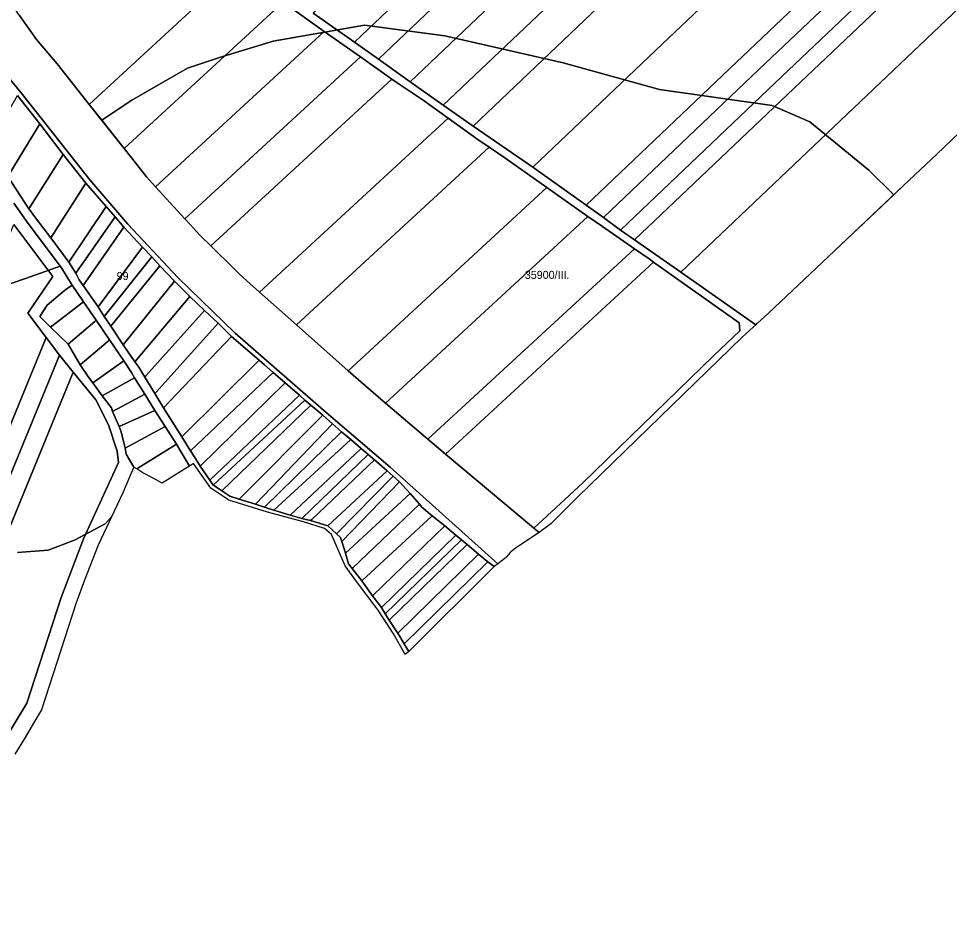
# Model space of a CAD drawing. Extents: x -545779 to -541342, y -1153413 to -1149956.
# Drawn here: x -543424 to -542843, y -1152006 to -1151443 of the extents above; entities that cross this region are included whole.
import ezdxf

# ---------------------------------------------------------------- set-up
doc = ezdxf.new("R2010")
doc.units = 0
for name, color, linetype in [('95560013', 7, 'Continuous'), ('95610013', 7, 'Continuous'), ('95620013', 7, 'Continuous'), ('95640013', 7, 'Continuous'), ('95660013', 7, 'Continuous')]:
    doc.layers.add(name, color=color, linetype=linetype)

msp = doc.modelspace()

# ---------------------------------------------------------------- linework, layer by layer
at = {"layer": '95560013'}
for points in [[(-543240.37, -1151439.86), (-543122.07, -1151327.37), (-543086.44, -1151336.23), (-543214.46, -1151457.97)], [(-543214.46, -1151457.97), (-543086.44, -1151336.23), (-543065.8, -1151341.37), (-543199.56, -1151468.55)], [(-543179.72, -1151482.68), (-543199.56, -1151468.55), (-543065.8, -1151341.37), (-543038.3, -1151348.21)], [(-543009.67, -1151355.33), (-543084.36, -1151426.35), (-543159.05, -1151497.37), (-543179.72, -1151482.68), (-543038.3, -1151348.21)], [(-543062.24, -1151436.05), (-543140.42, -1151510.39), (-543159.05, -1151497.37), (-543084.36, -1151426.35), (-543009.67, -1151355.33), (-542984.05, -1151361.71)], [(-543140.42, -1151510.39), (-543062.24, -1151436.05), (-542984.05, -1151361.71), (-542933.06, -1151374.39), (-543018.07, -1151455.22), (-543103.08, -1151536.05)], [(-543423.58, -1151441.25), (-543430.04, -1151432.08), (-543356.46, -1151364.23), (-543288.42, -1151412.25), (-543380.16, -1151496.84), (-543386.97, -1151488.23), (-543400.2, -1151471.61), (-543412.96, -1151456.3)], [(-543103.08, -1151536.05), (-543018.07, -1151455.22), (-542933.06, -1151374.39), (-542927.73, -1151375.72), (-542900.97, -1151380.24), (-542882.37, -1151381.53), (-542976.06, -1151470.62), (-543069.78, -1151559.73)], [(-542882.37, -1151381.53), (-542864.78, -1151382.75), (-542961.9, -1151475.1), (-543059.01, -1151567.44), (-543069.78, -1151559.73), (-542976.06, -1151470.62)], [(-542846.78, -1151383.71), (-542947.57, -1151479.54), (-543048.35, -1151575.37), (-543059.01, -1151567.44), (-542961.9, -1151475.1), (-542864.78, -1151382.75)], [(-542790.26, -1151387.63), (-542786.61, -1151388.71), (-542898.64, -1151495.22), (-543010.58, -1151601.66), (-543039.61, -1151581.56), (-542935.84, -1151482.89), (-542832.06, -1151384.22), (-542810.18, -1151384.97), (-542802.82, -1151385.95)], [(-542871.69, -1151547.61), (-542922.37, -1151595.59), (-542955.86, -1151627.29), (-542962.76, -1151633.49), (-542963.34, -1151634.01), (-542963.9, -1151634.52), (-543010.58, -1151601.66), (-542898.64, -1151495.22), (-542786.61, -1151388.71), (-542775.01, -1151392.15), (-542752.94, -1151403.28), (-542735.72, -1151413.15), (-542737.87, -1151417.23), (-542736.37, -1151418.2), (-542850.69, -1151527.98)], [(-543259.04, -1151432.91), (-543358.33, -1151524.47), (-543380.16, -1151496.84), (-543288.42, -1151412.25)], [(-543344.41, -1151542.05), (-543350.42, -1151534.47), (-543358.33, -1151524.47), (-543259.04, -1151432.91), (-543233.34, -1151451.27), (-543338.64, -1151548.36)], [(-543320.46, -1151568.25), (-543338.64, -1151548.36), (-543233.34, -1151451.27), (-543210.79, -1151467.12)], [(-543311.26, -1151578.3), (-543316.87, -1151572.17), (-543320.46, -1151568.25), (-543210.79, -1151467.12), (-543191.19, -1151481.04), (-543304.19, -1151585.24)], [(-543289.4, -1151599.75), (-543304.19, -1151585.24), (-543191.19, -1151481.04), (-543187.9, -1151483.38), (-543171.65, -1151494.16), (-543155.98, -1151505.49), (-543273.77, -1151614.1), (-543279.62, -1151608.92), (-543286.22, -1151602.87)], [(-543155.98, -1151505.49), (-543138.08, -1151518.43), (-543130.45, -1151523.63), (-543250.73, -1151634.54), (-543273.77, -1151614.1)], [(-543218.4, -1151663.21), (-543250.73, -1151634.54), (-543130.45, -1151523.63), (-543120.6, -1151530.35), (-543094.32, -1151548.8)], [(-543195.12, -1151683.41), (-543207.39, -1151672.98), (-543218.4, -1151663.21), (-543094.32, -1151548.8), (-543068.68, -1151566.81)], [(-543418.53, -1151627.26), (-543406.97, -1151642.49), (-543468.49, -1151792.18), (-543530.01, -1151941.87), (-543533.97, -1151930.97), (-543541.88, -1151911.96), (-543552.58, -1151876.88), (-543489.89, -1151724.34), (-543427.2, -1151571.8), (-543402.91, -1151604.4)], [(-543168.57, -1151706), (-543039.57, -1151587.04), (-543030.45, -1151593.35), (-543027.64, -1151595.49), (-543157.6, -1151715.34), (-543157.86, -1151715.12)], [(-542990.29, -1151653.95), (-543071.95, -1151733.2), (-543102.39, -1151761.68), (-543102.65, -1151761.47), (-543157.6, -1151715.34), (-543027.64, -1151595.49), (-543013.28, -1151605.56), (-542974.24, -1151633.22), (-542973.87, -1151638.29)], [(-543398.65, -1151653.46), (-543461.32, -1151805.95), (-543523.99, -1151958.44), (-543530.01, -1151941.87), (-543468.49, -1151792.18), (-543406.97, -1151642.49)], [(-543521.45, -1151965.43), (-543523.99, -1151958.44), (-543461.32, -1151805.95), (-543398.65, -1151653.46), (-543390.07, -1151664.07), (-543453.49, -1151818.38), (-543516.9, -1151972.68)], [(-543479.1, -1152005.99), (-543483.3, -1152003.71), (-543498.41, -1151992.69), (-543511.62, -1151981.09), (-543516.9, -1151972.68), (-543453.49, -1151818.38), (-543390.07, -1151664.07), (-543376.03, -1151681.34), (-543368.01, -1151696.98), (-543362.61, -1151713.54), (-543361.78, -1151720.51), (-543383.75, -1151768.25), (-543397.66, -1151804.81), (-543419.12, -1151870.85), (-543435.52, -1151898.22), (-543452.76, -1151939.02), (-543469.17, -1151983.54)]]:
    msp.add_lwpolyline(points, close=True, dxfattribs=at)
at = {"layer": '95610013'}
for points in [[(-542947.57, -1151479.54), (-542846.78, -1151383.71), (-542832.06, -1151384.22), (-542935.84, -1151482.89), (-543039.61, -1151581.56), (-543048.35, -1151575.37)], [(-543168.57, -1151706), (-543195.12, -1151683.41), (-543068.68, -1151566.81), (-543059.58, -1151573.2), (-543039.57, -1151587.04)]]:
    msp.add_lwpolyline(points, close=True, dxfattribs=at)
at = {"layer": '95620013'}
for points in [[(-543431.06, -1151541.91), (-543443.74, -1151523.48), (-543424.88, -1151491.22), (-543411.05, -1151509.1)], [(-543396.33, -1151528.09), (-543417.85, -1151562.13), (-543431.06, -1151541.91), (-543411.05, -1151509.1)], [(-543417.85, -1151562.13), (-543396.33, -1151528.09), (-543382.25, -1151546.08), (-543404.04, -1151580.22), (-543413.66, -1151567.75), (-543417.06, -1151563.2)], [(-543392.91, -1151595.33), (-543404.04, -1151580.22), (-543382.25, -1151546.08), (-543369.53, -1151560.74)], [(-543388.58, -1151602.2), (-543392.91, -1151595.33), (-543369.53, -1151560.74), (-543363.99, -1151567.2)], [(-543363.99, -1151567.2), (-543358.52, -1151573.53), (-543383.9, -1151609.97), (-543386.4, -1151606.53), (-543388.58, -1151602.2)], [(-543374.64, -1151623.4), (-543383.9, -1151609.97), (-543358.52, -1151573.53), (-543346.88, -1151586.09)], [(-543370.78, -1151629.43), (-543374.64, -1151623.4), (-543346.88, -1151586.09), (-543341.09, -1151592.14)], [(-543336, -1151597.73), (-543366.59, -1151635.38), (-543370.78, -1151629.43), (-543341.09, -1151592.14)], [(-543336, -1151597.73), (-543326.96, -1151607.22), (-543358.99, -1151647.05), (-543366.59, -1151635.38)], [(-543383.68, -1151620.16), (-543404.26, -1151636.1), (-543410.94, -1151629.34), (-543406.39, -1151622.22), (-543395.57, -1151613.08), (-543390.73, -1151609.82)], [(-543326.96, -1151607.22), (-543317.23, -1151616.88), (-543351.67, -1151657.74), (-543358.99, -1151647.05)], [(-543351.67, -1151657.74), (-543317.23, -1151616.88), (-543308.05, -1151625.71), (-543344.71, -1151666.45), (-543345.38, -1151667.2), (-543349.1, -1151661.08)], [(-543393.26, -1151646.72), (-543404.26, -1151636.1), (-543383.68, -1151620.16), (-543375.77, -1151631.75), (-543376.67, -1151632.52)], [(-543338.41, -1151676.71), (-543339.11, -1151677.5), (-543345.38, -1151667.2), (-543344.71, -1151666.45), (-543308.05, -1151625.71), (-543299.7, -1151633.54)], [(-543375.77, -1151631.75), (-543367.41, -1151644), (-543368.27, -1151644.72), (-543385.79, -1151659.49), (-543393.26, -1151646.72), (-543376.67, -1151632.52)], [(-543339.11, -1151677.5), (-543338.41, -1151676.71), (-543299.7, -1151633.54), (-543291.25, -1151641.87), (-543333.74, -1151686.33)], [(-543367.41, -1151644), (-543358.52, -1151657.03), (-543377.93, -1151670.81), (-543380.54, -1151667.3), (-543385.79, -1151659.49), (-543368.27, -1151644.72)], [(-543273.98, -1151656.74), (-543322.26, -1151704.61), (-543333.74, -1151686.33), (-543291.25, -1151641.87)], [(-543351.88, -1151667.61), (-543372.12, -1151679.02), (-543377.93, -1151670.81), (-543358.52, -1151657.03), (-543353.82, -1151664.27)], [(-543322.26, -1151704.61), (-543273.98, -1151656.74), (-543270.64, -1151659.61), (-543265.26, -1151664.33), (-543316.8, -1151713.2)], [(-543257.86, -1151670.85), (-543310.9, -1151722.83), (-543312.74, -1151719.8), (-543316.8, -1151713.2), (-543265.26, -1151664.33)], [(-543365.53, -1151688.62), (-543366.14, -1151686.46), (-543372.12, -1151679.02), (-543351.88, -1151667.61), (-543345.5, -1151677.89)], [(-543248.85, -1151678.58), (-543304.87, -1151731.69), (-543310.9, -1151722.83), (-543257.86, -1151670.85)], [(-543365.53, -1151688.62), (-543345.5, -1151677.89), (-543339.14, -1151688.04), (-543361.47, -1151698.1)], [(-543304.87, -1151731.69), (-543248.85, -1151678.58), (-543245.42, -1151681.55), (-543302.64, -1151734.66)], [(-543302.64, -1151734.66), (-543245.42, -1151681.55), (-543241.77, -1151684.73), (-543297.28, -1151738.29), (-543301.9, -1151735.16)], [(-543332.76, -1151698.02), (-543357.78, -1151711.52), (-543360.15, -1151701.38), (-543361.47, -1151698.1), (-543339.14, -1151688.04)], [(-543286.4, -1151743.51), (-543292.3, -1151741.64), (-543297.28, -1151738.29), (-543241.77, -1151684.73), (-543234.33, -1151691.06)], [(-543234.33, -1151691.06), (-543228.27, -1151696.33), (-543276.32, -1151746.7), (-543286.4, -1151743.51)], [(-543349.79, -1151724.17), (-543350.45, -1151724.58), (-543352.26, -1151723.45), (-543357.05, -1151715.3), (-543357.78, -1151711.52), (-543332.76, -1151698.02), (-543325.58, -1151709.18)], [(-543228.27, -1151696.33), (-543222.62, -1151701.37), (-543270.61, -1151748.52), (-543276.32, -1151746.7)], [(-543222.62, -1151701.37), (-543216.77, -1151706.3), (-543264.78, -1151750.28), (-543268.23, -1151749.27), (-543270.61, -1151748.52)], [(-543346.65, -1151726.93), (-543350.45, -1151724.58), (-543349.79, -1151724.17), (-543325.58, -1151709.18), (-543317.45, -1151722.93), (-543320.53, -1151724.8), (-543334.68, -1151733.4), (-543334.98, -1151733.24), (-543340.17, -1151730.43)], [(-543264.78, -1151750.28), (-543216.77, -1151706.3), (-543210.37, -1151711.78), (-543254.56, -1151753.4)], [(-543254.56, -1151753.4), (-543210.37, -1151711.78), (-543206.02, -1151715.6), (-543247.33, -1151755.54)], [(-543241.84, -1151756.9), (-543247.33, -1151755.54), (-543206.02, -1151715.6), (-543202.07, -1151718.81), (-543241.17, -1151756.26)], [(-543241.84, -1151756.9), (-543241.17, -1151756.26), (-543202.07, -1151718.81), (-543194.01, -1151725.87), (-543231.13, -1151760.18)], [(-543231.13, -1151760.18), (-543194.01, -1151725.87), (-543190.22, -1151729.01), (-543225.55, -1151764.93), (-543225.72, -1151765.1)], [(-543190.22, -1151729.01), (-543186.3, -1151732.58), (-543222.43, -1151769.99), (-543223.16, -1151767.42), (-543225.72, -1151765.1), (-543225.55, -1151764.93)], [(-543186.3, -1151732.58), (-543179.7, -1151740.03), (-543220.06, -1151777.21), (-543222.43, -1151769.99)], [(-543220.06, -1151777.21), (-543179.7, -1151740.03), (-543173.92, -1151746.6), (-543215.99, -1151786.73), (-543218.13, -1151783.86)], [(-543173.92, -1151746.6), (-543172.31, -1151748.41), (-543165.9, -1151753.83), (-543209.98, -1151794.57), (-543215.99, -1151786.73)], [(-543209.98, -1151794.57), (-543165.9, -1151753.83), (-543158.14, -1151760.23), (-543203.16, -1151803.88)], [(-543151.28, -1151765.95), (-543197.66, -1151811.2), (-543203.16, -1151803.88), (-543158.14, -1151760.23)], [(-543195.36, -1151815.2), (-543197.66, -1151811.2), (-543151.28, -1151765.95), (-543147.58, -1151768.97)], [(-543147.58, -1151768.97), (-543144.14, -1151771.84), (-543192.89, -1151819.14), (-543195.36, -1151815.2)], [(-543187.39, -1151827.29), (-543188.01, -1151826.44), (-543192.89, -1151819.14), (-543144.14, -1151771.84), (-543137.04, -1151777.74)], [(-543187.39, -1151827.29), (-543137.04, -1151777.74), (-543131.21, -1151782.64), (-543183.43, -1151833.8)], [(-543183.43, -1151833.8), (-543131.21, -1151782.64), (-543127.26, -1151785.58), (-543180.59, -1151838.55)]]:
    msp.add_lwpolyline(points, close=True, dxfattribs=at)
at = {"layer": '95640013'}
for points in [[(-543240.37, -1151439.86), (-543214.46, -1151457.97), (-543199.56, -1151468.55), (-543179.72, -1151482.68), (-543159.05, -1151497.37), (-543140.42, -1151510.39), (-543103.08, -1151536.05), (-543069.78, -1151559.73), (-543059.01, -1151567.44), (-543048.35, -1151575.37), (-543039.61, -1151581.56), (-543010.58, -1151601.66), (-542963.9, -1151634.52), (-542967.43, -1151637.69), (-542967.65, -1151637.89), (-542970.14, -1151640.13), (-542972.32, -1151642.24), (-543074.97, -1151742.01), (-543091.89, -1151758.92), (-543099.2, -1151764.35), (-543102.39, -1151761.68), (-543071.95, -1151733.2), (-542990.29, -1151653.95), (-542973.87, -1151638.29), (-542974.24, -1151633.22), (-543013.28, -1151605.56), (-543027.64, -1151595.49), (-543030.45, -1151593.35), (-543039.57, -1151587.04), (-543059.58, -1151573.2), (-543068.68, -1151566.81), (-543094.32, -1151548.8), (-543120.6, -1151530.35), (-543130.45, -1151523.63), (-543138.08, -1151518.43), (-543155.98, -1151505.49), (-543171.65, -1151494.16), (-543187.9, -1151483.38), (-543191.19, -1151481.04), (-543210.79, -1151467.12), (-543233.34, -1151451.27), (-543259.04, -1151432.91)], [(-543423.58, -1151441.25), (-543412.96, -1151456.3), (-543400.2, -1151471.61), (-543386.97, -1151488.23), (-543380.16, -1151496.84), (-543358.33, -1151524.47), (-543350.42, -1151534.47), (-543344.41, -1151542.05), (-543338.64, -1151548.36), (-543320.46, -1151568.25), (-543316.87, -1151572.17), (-543311.26, -1151578.3), (-543304.19, -1151585.24), (-543289.4, -1151599.75), (-543286.22, -1151602.87), (-543279.62, -1151608.92), (-543273.77, -1151614.1), (-543250.73, -1151634.54), (-543218.4, -1151663.21), (-543207.39, -1151672.98), (-543195.12, -1151683.41), (-543168.57, -1151706), (-543157.86, -1151715.12), (-543157.6, -1151715.34), (-543102.65, -1151761.47), (-543102.39, -1151761.68), (-543099.2, -1151764.35), (-543112.08, -1151772.78), (-543113.27, -1151773.68), (-543116.9, -1151776.44), (-543117.19, -1151776.78), (-543118.26, -1151778.06), (-543119.5, -1151779.55), (-543119.82, -1151779.93), (-543123.16, -1151782.47), (-543125, -1151783.87), (-543192.1, -1151723.45), (-543232.12, -1151689.27), (-543288.94, -1151639.78), (-543324.56, -1151605.12), (-543355.96, -1151571.72), (-543379.7, -1151544.02), (-543422.57, -1151489.55), (-543430.64, -1151480.07)], [(-543430.64, -1151480.07), (-543422.57, -1151489.55), (-543379.7, -1151544.02), (-543355.96, -1151571.72), (-543324.56, -1151605.12), (-543288.94, -1151639.78), (-543232.12, -1151689.27), (-543192.1, -1151723.45), (-543125, -1151783.87), (-543127.26, -1151785.58), (-543131.21, -1151782.64), (-543137.04, -1151777.74), (-543144.14, -1151771.84), (-543147.58, -1151768.97), (-543151.28, -1151765.95), (-543158.14, -1151760.23), (-543165.9, -1151753.83), (-543172.31, -1151748.41), (-543173.92, -1151746.6), (-543179.7, -1151740.03), (-543186.3, -1151732.58), (-543190.22, -1151729.01), (-543194.01, -1151725.87), (-543202.07, -1151718.81), (-543206.02, -1151715.6), (-543210.37, -1151711.78), (-543216.77, -1151706.3), (-543222.62, -1151701.37), (-543228.27, -1151696.33), (-543234.33, -1151691.06), (-543241.77, -1151684.73), (-543245.42, -1151681.55), (-543248.85, -1151678.58), (-543257.86, -1151670.85), (-543265.26, -1151664.33), (-543270.64, -1151659.61), (-543273.98, -1151656.74), (-543291.25, -1151641.87), (-543299.7, -1151633.54), (-543308.05, -1151625.71), (-543317.23, -1151616.88), (-543326.96, -1151607.22), (-543336, -1151597.73), (-543341.09, -1151592.14), (-543346.88, -1151586.09), (-543358.52, -1151573.53), (-543363.99, -1151567.2), (-543369.53, -1151560.74), (-543382.25, -1151546.08), (-543396.33, -1151528.09), (-543411.05, -1151509.1), (-543424.88, -1151491.22)], [(-543431.06, -1151541.91), (-543417.85, -1151562.13), (-543417.06, -1151563.2), (-543413.66, -1151567.75), (-543404.04, -1151580.22), (-543392.91, -1151595.33), (-543388.58, -1151602.2), (-543386.4, -1151606.53), (-543383.9, -1151609.97), (-543374.64, -1151623.4), (-543370.78, -1151629.43), (-543366.59, -1151635.38), (-543358.99, -1151647.05), (-543351.67, -1151657.74), (-543349.1, -1151661.08), (-543345.38, -1151667.2), (-543339.11, -1151677.5), (-543333.74, -1151686.33), (-543322.26, -1151704.61), (-543316.8, -1151713.2), (-543312.74, -1151719.8), (-543310.9, -1151722.83), (-543304.87, -1151731.69), (-543302.64, -1151734.66), (-543301.9, -1151735.16), (-543297.28, -1151738.29), (-543292.3, -1151741.64), (-543286.4, -1151743.51), (-543276.32, -1151746.7), (-543270.61, -1151748.52), (-543268.23, -1151749.27), (-543264.78, -1151750.28), (-543254.56, -1151753.4), (-543247.33, -1151755.54), (-543241.84, -1151756.9), (-543231.13, -1151760.18), (-543225.72, -1151765.1), (-543223.16, -1151767.42), (-543222.43, -1151769.99), (-543220.06, -1151777.21), (-543218.13, -1151783.86), (-543215.99, -1151786.73), (-543209.98, -1151794.57), (-543203.16, -1151803.88), (-543197.66, -1151811.2), (-543195.36, -1151815.2), (-543192.89, -1151819.14), (-543188.01, -1151826.44), (-543187.39, -1151827.29), (-543183.43, -1151833.8), (-543180.59, -1151838.55), (-543182.72, -1151840.56), (-543190.17, -1151827.53), (-543199.69, -1151812.91), (-543213.26, -1151794.85), (-543220.28, -1151785.11), (-543228.8, -1151765.46), (-543233.24, -1151761.72), (-543246.29, -1151757.6), (-543268.84, -1151751.68), (-543293.01, -1151744.18), (-543304.27, -1151736.65), (-543315.01, -1151721.22), (-543317.45, -1151722.93), (-543325.58, -1151709.18), (-543332.76, -1151698.02), (-543339.14, -1151688.04), (-543345.5, -1151677.89), (-543351.88, -1151667.61), (-543353.82, -1151664.27), (-543358.52, -1151657.03), (-543367.41, -1151644), (-543375.77, -1151631.75), (-543383.68, -1151620.16), (-543390.73, -1151609.82), (-543393.9, -1151604.89), (-543397.39, -1151598.94), (-543418.36, -1151571.3), (-543427.14, -1151558.55)], [(-543427.14, -1151558.55), (-543418.36, -1151571.3), (-543397.39, -1151598.94), (-543393.9, -1151604.89), (-543390.73, -1151609.82), (-543395.57, -1151613.08), (-543406.39, -1151622.22), (-543410.94, -1151629.34), (-543404.26, -1151636.1), (-543393.26, -1151646.72), (-543385.79, -1151659.49), (-543380.54, -1151667.3), (-543377.93, -1151670.81), (-543372.12, -1151679.02), (-543366.14, -1151686.46), (-543365.53, -1151688.62), (-543361.47, -1151698.1), (-543360.15, -1151701.38), (-543357.78, -1151711.52), (-543357.05, -1151715.3), (-543352.26, -1151723.45), (-543354.57, -1151728.77), (-543359.23, -1151739.5), (-543374.52, -1151772.12), (-543383.06, -1151794.08), (-543388.23, -1151808.14), (-543409.96, -1151875.02), (-543414.3, -1151882.41), (-543417.79, -1151888.34), (-543420.11, -1151892.3), (-543426.58, -1151902.76)], [(-543435.52, -1151898.22), (-543419.12, -1151870.85), (-543397.66, -1151804.81), (-543383.75, -1151768.25), (-543361.78, -1151720.51), (-543362.61, -1151713.54), (-543368.01, -1151696.98), (-543376.03, -1151681.34), (-543390.07, -1151664.07), (-543398.65, -1151653.46), (-543406.97, -1151642.49), (-543418.53, -1151627.26), (-543402.91, -1151604.4), (-543427.2, -1151571.8)]]:
    msp.add_lwpolyline(points, dxfattribs=at)
at = {"layer": '95660013'}
for points in [[(-542736.37, -1151418.2), (-542850.69, -1151527.98), (-542871.69, -1151547.61), (-542877.74, -1151553.338), (-542893.213, -1151537.863), (-542930.077, -1151507.703), (-542953.535, -1151497.649), (-543023.908, -1151487.596), (-543084.228, -1151470.84), (-543157.952, -1151454.085), (-543208.219, -1151447.382), (-543265.189, -1151457.436), (-543298.7, -1151467.489), (-543318.807, -1151474.192), (-543353.575, -1151494.298), (-543372.304, -1151506.783), (-543380.16, -1151496.84), (-543386.97, -1151488.23), (-543400.2, -1151471.61), (-543412.96, -1151456.3), (-543423.58, -1151441.25)], [(-543423.58, -1151441.25), (-543412.96, -1151456.3), (-543400.2, -1151471.61), (-543386.97, -1151488.23), (-543380.16, -1151496.84), (-543372.304, -1151506.783), (-543358.33, -1151524.47), (-543350.42, -1151534.47), (-543344.41, -1151542.05), (-543338.64, -1151548.36), (-543320.46, -1151568.25), (-543316.87, -1151572.17), (-543311.26, -1151578.3), (-543304.19, -1151585.24), (-543289.4, -1151599.75), (-543286.22, -1151602.87), (-543279.62, -1151608.92), (-543273.77, -1151614.1), (-543250.73, -1151634.54), (-543218.4, -1151663.21), (-543207.39, -1151672.98), (-543195.12, -1151683.41), (-543168.57, -1151706), (-543157.86, -1151715.12), (-543157.6, -1151715.34), (-543102.65, -1151761.47), (-543102.39, -1151761.68), (-543099.2, -1151764.35), (-543112.08, -1151772.78), (-543113.27, -1151773.68), (-543116.9, -1151776.44), (-543117.19, -1151776.78), (-543118.26, -1151778.06), (-543119.5, -1151779.55), (-543119.82, -1151779.93), (-543123.16, -1151782.47), (-543125, -1151783.87), (-543127.26, -1151785.58), (-543180.59, -1151838.55), (-543182.72, -1151840.56), (-543190.17, -1151827.53), (-543199.69, -1151812.91), (-543213.26, -1151794.85), (-543220.28, -1151785.11), (-543228.8, -1151765.46), (-543233.24, -1151761.72), (-543246.29, -1151757.6), (-543268.84, -1151751.68), (-543293.01, -1151744.18), (-543304.27, -1151736.65), (-543315.01, -1151721.22), (-543317.45, -1151722.93), (-543320.53, -1151724.8), (-543334.68, -1151733.4), (-543334.98, -1151733.24), (-543340.17, -1151730.43), (-543346.65, -1151726.93), (-543350.45, -1151724.58), (-543352.26, -1151723.45), (-543357.05, -1151715.3), (-543357.78, -1151711.52), (-543360.15, -1151701.38), (-543361.47, -1151698.1), (-543365.53, -1151688.62), (-543366.14, -1151686.46), (-543372.12, -1151679.02), (-543377.93, -1151670.81), (-543380.54, -1151667.3), (-543385.79, -1151659.49), (-543393.26, -1151646.72), (-543404.26, -1151636.1), (-543410.94, -1151629.34), (-543406.39, -1151622.22), (-543395.57, -1151613.08), (-543390.73, -1151609.82), (-543393.9, -1151604.89), (-543397.39, -1151598.94), (-543398.209, -1151597.86), (-543418.36, -1151571.3), (-543427.14, -1151558.55)], [(-543427.14, -1151558.55), (-543418.36, -1151571.3), (-543398.209, -1151597.86), (-543419.86, -1151605.73), (-543450.482, -1151615.938)], [(-543450.482, -1151615.938), (-543419.86, -1151605.73), (-543398.209, -1151597.86), (-543397.39, -1151598.94), (-543393.9, -1151604.89), (-543390.73, -1151609.82), (-543395.57, -1151613.08), (-543406.39, -1151622.22), (-543410.94, -1151629.34), (-543404.26, -1151636.1), (-543393.26, -1151646.72), (-543385.79, -1151659.49), (-543380.54, -1151667.3), (-543377.93, -1151670.81), (-543372.12, -1151679.02), (-543366.14, -1151686.46), (-543365.53, -1151688.62), (-543361.47, -1151698.1), (-543360.15, -1151701.38), (-543357.78, -1151711.52), (-543357.05, -1151715.3), (-543352.26, -1151723.45), (-543354.57, -1151728.77), (-543359.23, -1151739.5), (-543366.29, -1151754.562), (-543366.29, -1151754.562), (-543370.096, -1151758.846), (-543389.237, -1151769.054), (-543405.825, -1151775.434), (-543424.963, -1151776.71)], [(-543424.963, -1151776.71), (-543405.825, -1151775.434), (-543389.237, -1151769.054), (-543370.096, -1151758.846), (-543366.29, -1151754.562), (-543374.52, -1151772.12), (-543383.06, -1151794.08), (-543388.23, -1151808.14), (-543409.96, -1151875.02), (-543414.3, -1151882.41), (-543417.79, -1151888.34), (-543420.11, -1151892.3), (-543426.58, -1151902.76)]]:
    msp.add_lwpolyline(points, dxfattribs=at)
msp.add_lwpolyline([(-542893.213, -1151537.863), (-542877.74, -1151553.338), (-542922.37, -1151595.59), (-542955.86, -1151627.29), (-542962.76, -1151633.49), (-542963.34, -1151634.01), (-542963.9, -1151634.52), (-542967.43, -1151637.69), (-542967.65, -1151637.89), (-542970.14, -1151640.13), (-542972.32, -1151642.24), (-543074.97, -1151742.01), (-543091.89, -1151758.92), (-543099.2, -1151764.35), (-543102.39, -1151761.68), (-543102.65, -1151761.47), (-543157.6, -1151715.34), (-543157.86, -1151715.12), (-543168.57, -1151706), (-543195.12, -1151683.41), (-543207.39, -1151672.98), (-543218.4, -1151663.21), (-543250.73, -1151634.54), (-543273.77, -1151614.1), (-543279.62, -1151608.92), (-543286.22, -1151602.87), (-543289.4, -1151599.75), (-543304.19, -1151585.24), (-543311.26, -1151578.3), (-543316.87, -1151572.17), (-543320.46, -1151568.25), (-543338.64, -1151548.36), (-543344.41, -1151542.05), (-543350.42, -1151534.47), (-543358.33, -1151524.47), (-543372.304, -1151506.783), (-543353.575, -1151494.298), (-543318.807, -1151474.192), (-543298.7, -1151467.489), (-543265.189, -1151457.436), (-543208.219, -1151447.382), (-543157.952, -1151454.085), (-543084.228, -1151470.84), (-543023.908, -1151487.596), (-542953.535, -1151497.649), (-542930.077, -1151507.703)], close=True, dxfattribs=at)

# ---------------------------------------------------------------- texts
for s, rotation, p in [('35900/III.', 360, (-543108.089, -1151605.866)), ('99', 0, (-543362.99, -1151606.561))]:
    msp.add_text(s, height=5, rotation=rotation, dxfattribs=at).set_placement(p)

doc.saveas('drawing.dxf')
